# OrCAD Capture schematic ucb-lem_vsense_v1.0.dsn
size C; title: UCB-LEM_LV-Sense; rev: 1.0; company: University of Arkansas (NCREPT); note: 700 W. Research Center Blvd.; note: Fayetteville, AR 72701
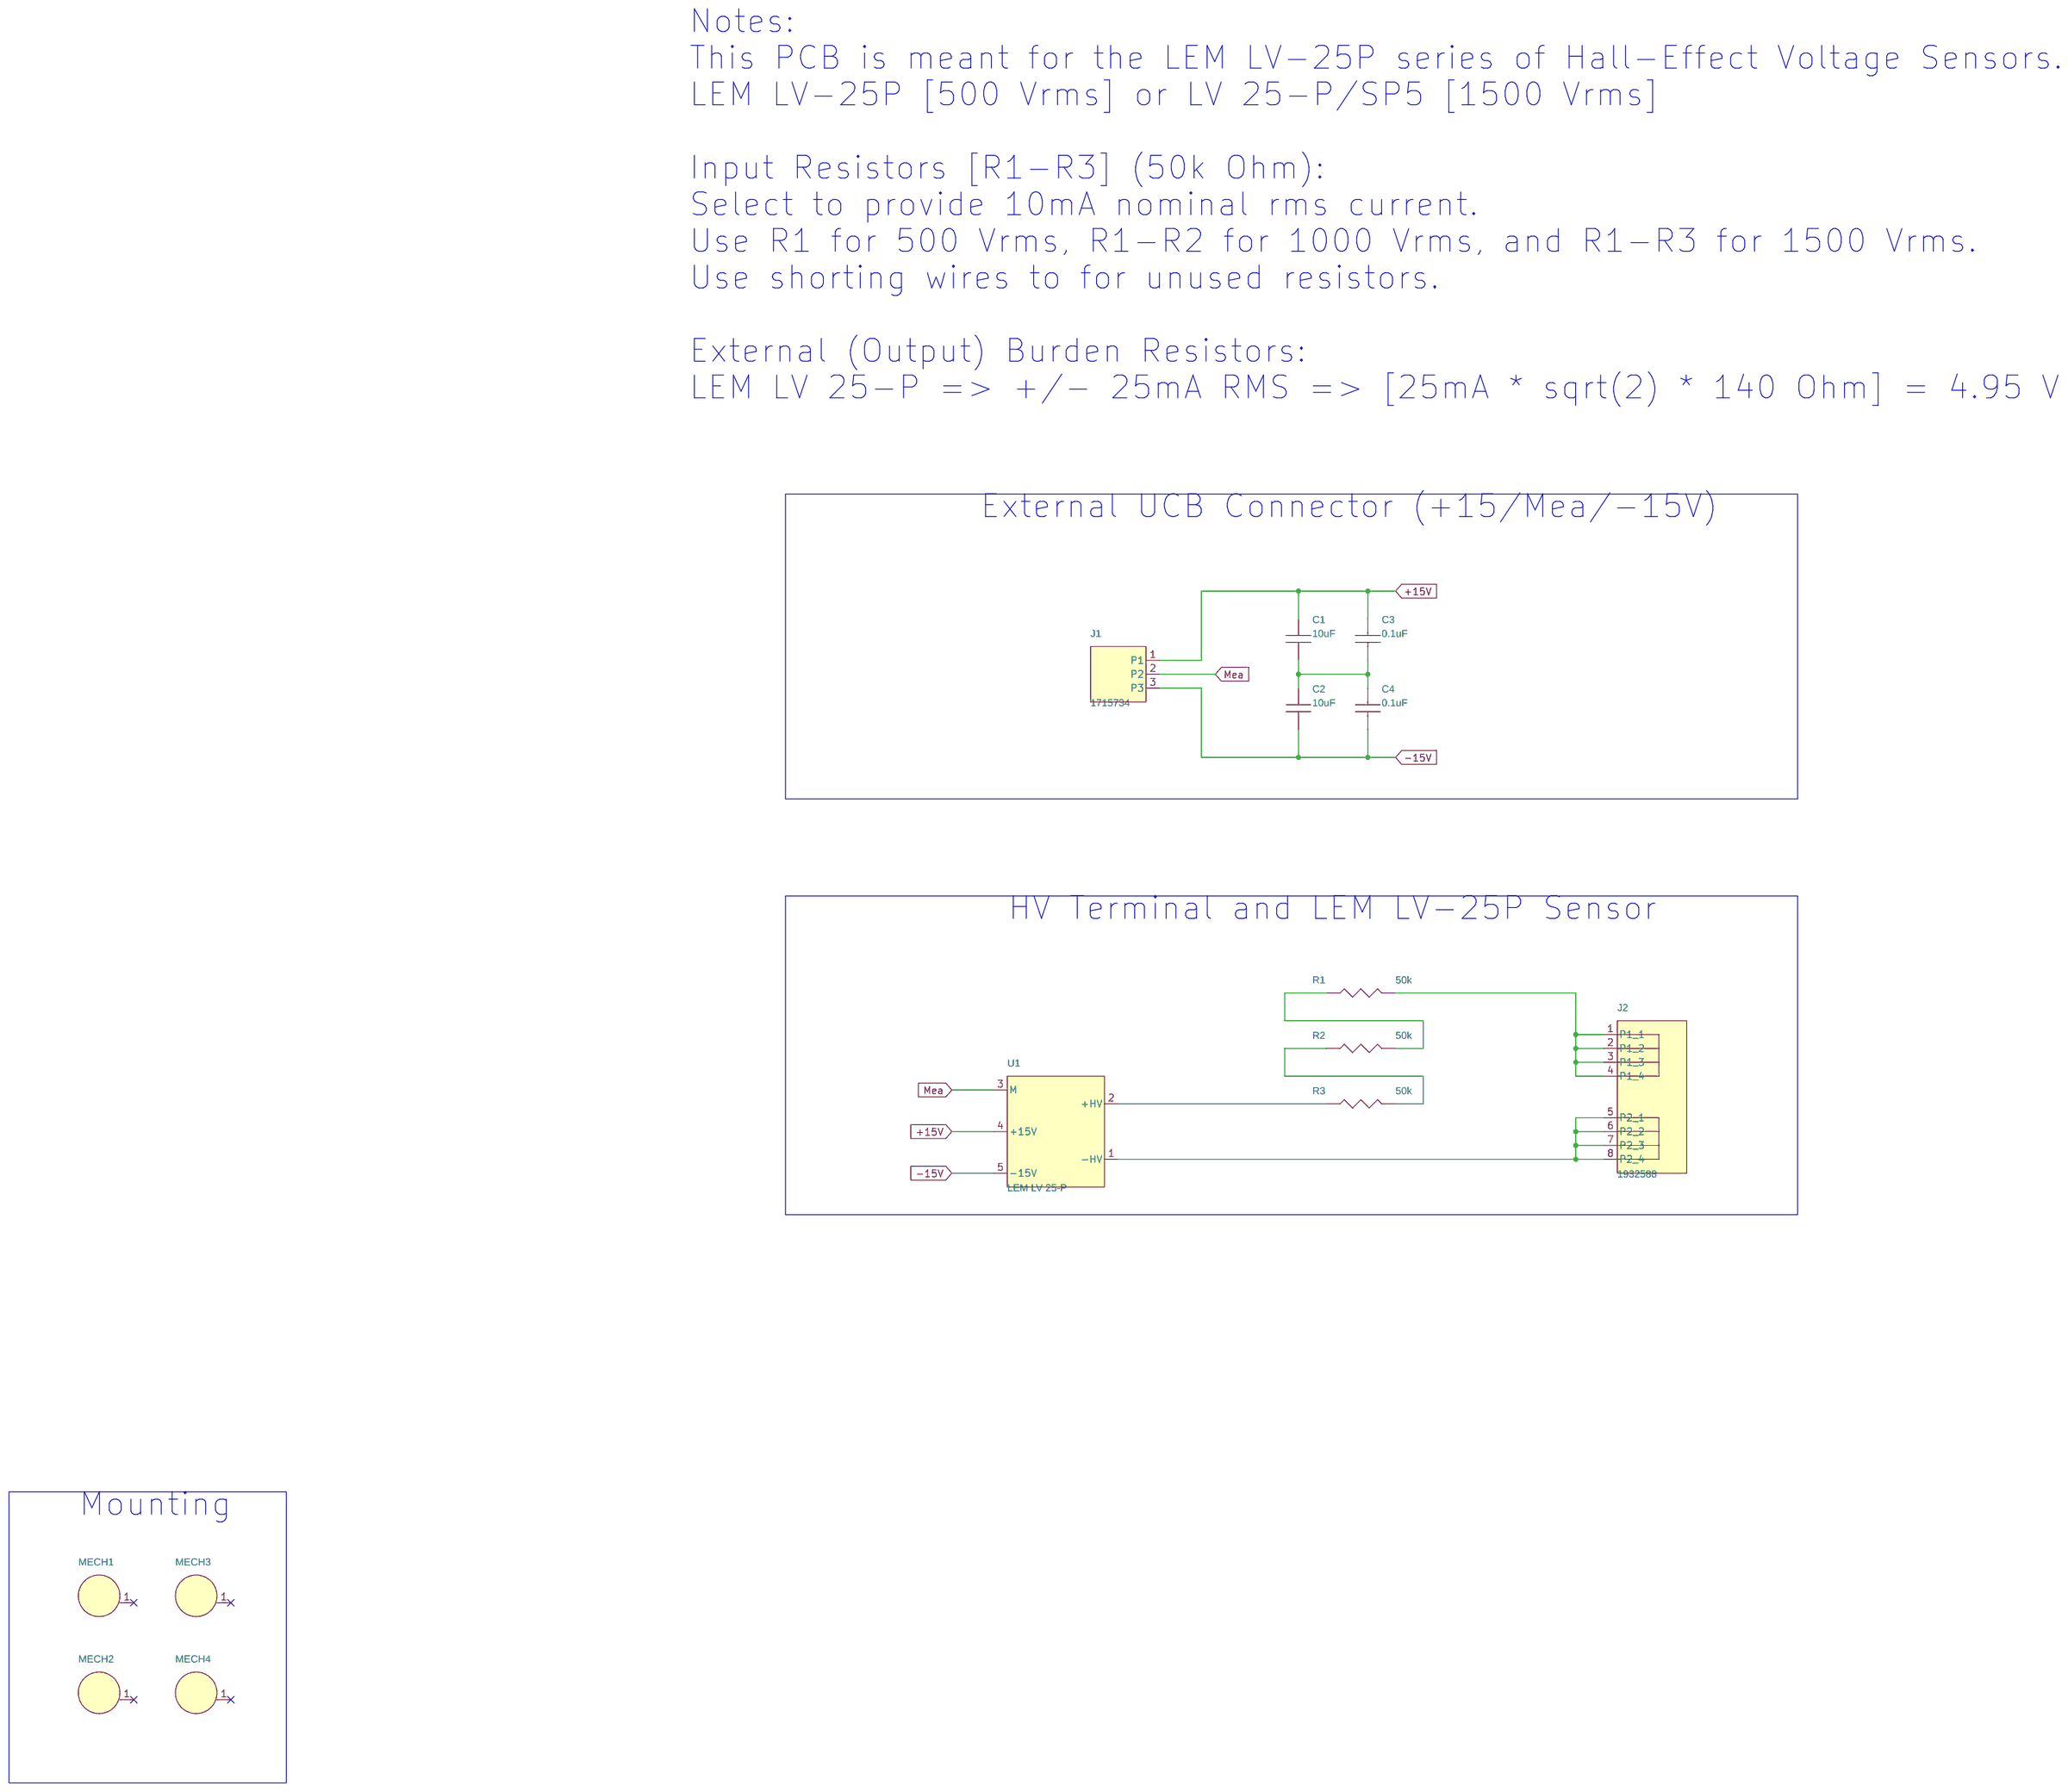
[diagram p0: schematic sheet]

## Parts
C1  10uF  [C_1206]
C2  10uF  [C_1206]
C3  0.1uF  [C_0603]
C4  0.1uF  [C_0603]
J1  1715734  [1715734]
J2  1932588  [PHOENIX_1932588]
MECH1  Mech_Hole  [4-40_SCREW]
MECH2  Mech_Hole  [4-40_SCREW]
MECH3  Mech_Hole  [4-40_SCREW]
MECH4  Mech_Hole  [4-40_SCREW]
R1  50k  [R_RS10]
R2  50k  [R_RS10]
R3  50k  [R_RS10]
U1  LEM LV 25-P  [LEM_LV-25-P]

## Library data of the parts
C1 C2 = CAP_NP: 10µF ±20% 35V X7R MLCC; Manufacturer: TDK; Manufacturer_Part_Number: C3216X7R1V106M160AC; Part_Number: Cap-00002; Tolerance: 20%; Voltage: 35V; Datasheet: TDK-mlcc_commercial_general_en.pdf
C3 C4 = CAP_NP: 0.1µF ±10% 50V X7R MLCC; Manufacturer: TDK; Manufacturer_Part_Number: C1608X7R1H104K080AA; Part_Number: Cap-00001; Tolerance: 10%; Voltage: 50V; Datasheet: TDK-mlcc_commercial_general_en.pdf
J1 = Connector-3: PCB Terminal Block, 3-position, 90 degrees, 5.08mm; Manufacturer: Phoenix Contact; Part_Number: Con-00007; Rating: 17.5A; STEP_Model: 1715734.stp; Voltage: 400V; Datasheet: PhoenixContact-1715734.pdf
J2 = HV_Connector-2: PCB Terminal Block, 2-position, 90 degrees, 15mm, 1kV; Manufacturer: Phoenix Contact; Part_Number: TMP-241; Rating: 125A; STEP_Model: Phoenix_1932588.stp; Voltage: 1kV; Datasheet: Phoenix-1932588.pdf
MECH1-MECH4 = Mech_Hole: Mounting Hole for 4-40 Screw, 0.125"; Part_Number: Con-00005
R1-R3 = R-Standard: 50 kOhm, 1%, 10W; Manufacturer: Vishay; Manufacturer_Part_Number: RS01050K00FE12; Part_Number: TMP-240; Rating: 10W; Tolerance: 1%; Datasheet: Vishay-rsns-226497.pdf
U1 = LEM-LV25-P: Isolated LEM Voltage Sensor (500Vac/1500Vac); Manufacturer: LEM; Manufacturer_Part_Number: LV 25-P; Part_Number: TMP-238; Datasheet: LEM-lv_25-p_sp5.pdf

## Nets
+15V: C1.1 C3.1 J1.1(P1) U1.4(+15V)
-15V: C2.2 C4.2 J1.3(P3) U1.5(-15V)
Mea: J1.2(P2) U1.3(M)
N61188: C1.2 C2.1 C3.2 C4.1
N61680: J2.1(P1) J2.2(P1) J2.3(P1) J2.4(P1) R1.2
N61699: R1.1 R2.2
N61724: R2.1 R3.2
N61749: R3.1 U1.2(+HV)
N61761: J2.5(P2_1) J2.6(P2_2) J2.7(P2_3) J2.8(P2_4) U1.1(-HV)

Not connected (* = marked no-connect by the designer): MECH1 1*; MECH2 1*; MECH3 1*; MECH4 1*

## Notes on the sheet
- Notes:
  This PCB is meant for the LEM LV-25P series of Hall-Effect Voltage Sensors.
  LEM LV-25P [500 Vrms] or LV 25-P/SP5 [1500 Vrms]
  Input Resistors [R1-R3] (50k Ohm):
  Select to provide 10mA nominal rms current.
  Use R1 for 500 Vrms, R1-R2 for 1000 Vrms, and R1-R3 for 1500 Vrms.
  Use shorting wires to for unused resistors.
  External (Output) Burden Resistors:
  LEM LV 25-P => +/- 25mA RMS => [25mA * sqrt(2) * 140 Ohm] = 4.95 V
- External UCB Connector (+15/Mea/-15V)
- HV Terminal and LEM LV-25P Sensor
- Mounting
